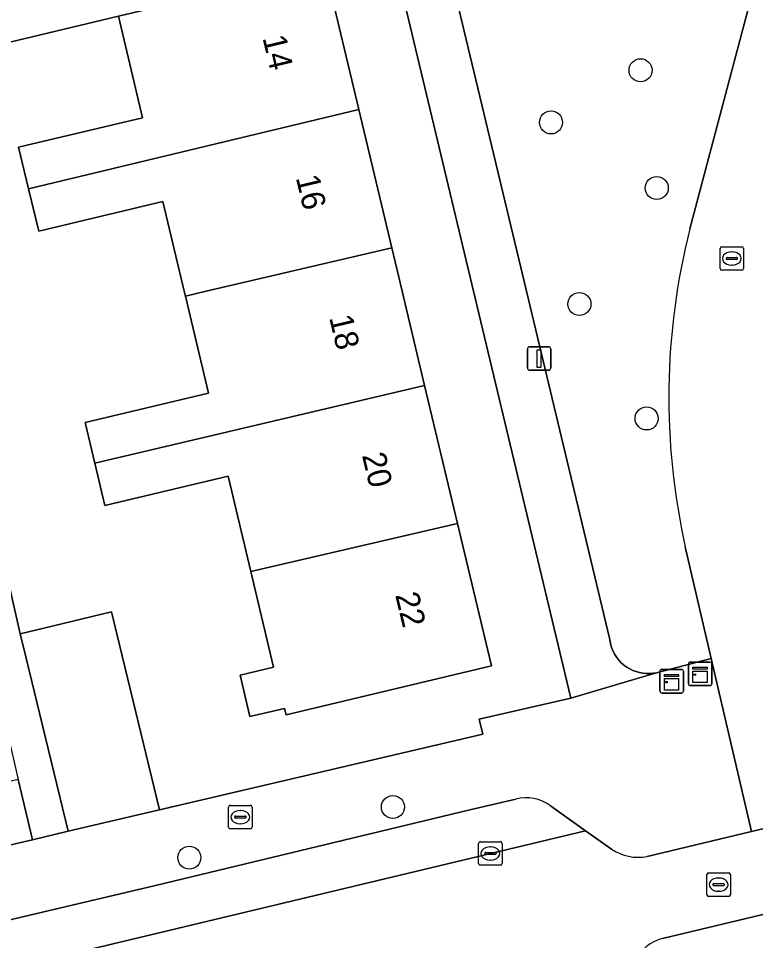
# Model space of a CAD drawing. Extents: x 158031 to 159244, y 380104 to 381214.
# Drawn here: x 158653.35 to 158684.67, y 380722.4 to 380761.59 of the extents above; entities that cross this region are included whole.
import ezdxf

# ---------------------------------------------------------------- set-up
doc = ezdxf.new("R2010")
doc.units = 0
for name, color, linetype in [('IMGEO_Boom', 7, 'Continuous'), ('IMGEO_Brandkraan', 7, 'Continuous'), ('IMGEO_Erf', 7, 'Continuous'), ('IMGEO_Fietspad_open', 7, 'Continuous'), ('IMGEO_Groenvoorziening', 7, 'Continuous'), ('IMGEO_Kast', 7, 'Continuous'), ('IMGEO_Kolk', 7, 'Continuous'), ('IMGEO_Lichtmast', 7, 'Continuous'), ('IMGEO_Muur', 7, 'Continuous'), ('IMGEO_Pand', 7, 'Continuous'), ('IMGEO_Pand_nummerreeks', 7, 'Continuous'), ('IMGEO_Parkeervlak_open', 7, 'Continuous'), ('IMGEO_Rijbaan_lokaal_gesloten', 7, 'Continuous'), ('IMGEO_Rioolput', 7, 'Continuous'), ('IMGEO_Voetpad_open', 7, 'Continuous')]:
    doc.layers.add(name, color=color, linetype=linetype)

msp = doc.modelspace()

# ---------------------------------------------------------------- linework, layer by layer
at = {"layer": 'IMGEO_Boom'}
for centre in [(158679.783, 380759.387), (158675.981, 380757.169), (158680.473, 380754.38), (158677.187, 380749.451), (158680.04, 380744.588), (158669.26, 380728.079), (158660.611, 380725.925)]:
    msp.add_circle(centre, 0.489, dxfattribs=at)
at = {"layer": 'IMGEO_Brandkraan'}
for p, q in [((158662.278, 380727.221), (158662.278, 380728.073)), ((158662.353, 380728.147), (158663.205, 380728.147)), ((158663.279, 380728.073), (158663.279, 380727.221)), ((158662.537, 380727.641), (158662.537, 380727.653)), ((158662.975, 380727.604), (158662.577, 380727.604)), ((158662.58, 380727.69), (158662.978, 380727.69)), ((158662.766, 380727.927), (158662.791, 380727.927)), ((158663.021, 380727.653), (158663.021, 380727.641)), ((158662.789, 380727.367), (158662.764, 380727.367)), ((158663.205, 380727.147), (158662.353, 380727.147))]:
    msp.add_line(p, q, dxfattribs=at)
for points in [[(158662.278, 380727.221), (158662.278, 380728.073)], [(158662.353, 380728.147), (158663.205, 380728.147)], [(158663.279, 380728.073), (158663.279, 380727.221)], [(158663.205, 380727.147), (158662.353, 380727.147)]]:
    msp.add_lwpolyline(points, dxfattribs=at)
for centre, radius, start, end in [((158662.355, 380728.071), 0.0765, 91.552, 178.448), ((158662.355, 380728.071), 0.0765, 91.552, 178.448), ((158663.203, 380728.071), 0.0765, 1.552, 88.448), ((158663.203, 380728.071), 0.0765, 1.552, 88.448), ((158662.577, 380727.65), 0.0403, 85.8775, 175.7526), ((158662.574, 380727.64), 0.0366, 178.938, 274.7102), ((158662.978, 380727.647), 0.043, 264.8664, 352.4533), ((158662.982, 380727.652), 0.0386, 1.7309, 96.639), ((158662.355, 380727.223), 0.0765, 181.552, 268.448), ((158662.355, 380727.223), 0.0765, 181.552, 268.448), ((158663.203, 380727.223), 0.0765, 271.552, 358.448), ((158663.203, 380727.223), 0.0765, 271.552, 358.448)]:
    msp.add_arc(centre, radius, start, end, dxfattribs=at)
for centre, major_axis, ratio, start_param, end_param in [((158662.765, 380727.647), (-0.387, 0.002), 0.722429, 4.712389, 7.853982), ((158662.79, 380727.647), (-0.39, 0.002), 0.717154, 1.570796, 4.712389)]:
    msp.add_ellipse(centre, major_axis=major_axis, ratio=ratio, start_param=start_param, end_param=end_param, dxfattribs=at)
at = {"layer": 'IMGEO_Erf'}
for points in [[(158650.69, 380747.468), (158653.428, 380735.432), (158654.421, 380735.673), (158657.309, 380736.372), (158659.347, 380727.957), (158673.077, 380731.178), (158672.928, 380731.803), (158676.826, 380732.7), (158672.691, 380750), (158669.232, 380764.469)], [(158666.369, 380763.785), (158667.815, 380757.714), (158669.215, 380751.84), (158669.653, 380750), (158670.609, 380745.985), (158672.004, 380740.13), (158673.447, 380734.071), (158664.719, 380731.999), (158664.655, 380732.269), (158663.184, 380731.919), (158662.765, 380733.684), (158664.186, 380734.021), (158663.223, 380738.078), (158662.259, 380742.138), (158657.022, 380740.894), (158656.594, 380742.694), (158656.184, 380744.42), (158661.424, 380745.664), (158660.441, 380749.791), (158660.391, 380750), (158659.485, 380753.803), (158654.21, 380752.543), (158653.779, 380754.347), (158653.357, 380756.114), (158658.626, 380757.371), (158657.602, 380761.691), (158647.702, 380759.325)], [(158633.943, 380722.518), (158641.525, 380724.316), (158641.632, 380723.796), (158651.055, 380726.009), (158653.942, 380726.687), (158653.341, 380729.248), (158650.454, 380728.57), (158649.015, 380734.699), (158651.902, 380735.377), (158646.366, 380758.949), (158636.257, 380756.574)]]:
    msp.add_lwpolyline(points, dxfattribs=at)
at = {"layer": 'IMGEO_Fietspad_open'}
for points in [[(158706.116, 380846.84), (158705.38, 380841.883), (158704.294, 380836.939), (158703.345, 380833.438), (158702.672, 380830.956), (158702.438, 380830.095), (158702.064, 380828.716), (158698.689, 380816.265), (158694.658, 380800.796), (158694.343, 380799.586), (158694.028, 380798.377), (158693.242, 380795.503), (158691.914, 380790.494), (158681.877, 380752.64)], [(158681.687, 380739.13), (158682.788, 380734.39), (158684.497, 380727.034), (158687.897, 380727.847), (158686.923, 380732.453), (158685.37, 380739.805)]]:
    msp.add_lwpolyline(points, dxfattribs=at)
msp.add_arc((158710.112, 380745.487), 29.127, 165.7831, 192.6055, dxfattribs=at)
at = {"layer": 'IMGEO_Groenvoorziening'}
for points in [[(158681.877, 380752.64), (158691.914, 380790.494), (158676.397, 380786.904), (158675.713, 380786.597), (158675.262, 380786.166), (158674.923, 380785.504), (158674.902, 380784.494), (158679.794, 380763.903), (158677.848, 380763.441), (158672.026, 380787.946)], [(158672.055, 380762.058), (158674.94, 380750), (158678.469, 380735.251), (158678.488, 380735.105), (158678.521, 380734.961), (158678.566, 380734.82), (158678.624, 380734.685), (158678.693, 380734.554), (158678.774, 380734.431), (158678.866, 380734.315), (158678.967, 380734.208), (158679.078, 380734.111), (158679.197, 380734.023), (158679.323, 380733.947), (158679.456, 380733.882), (158679.593, 380733.829), (158679.735, 380733.789), (158679.88, 380733.762), (158680.027, 380733.748), (158680.175, 380733.747), (158680.322, 380733.759), (158680.401, 380733.771), (158682.788, 380734.39), (158681.687, 380739.13)]]:
    msp.add_lwpolyline(points, dxfattribs=at)
msp.add_arc((158710.112, 380745.487), 29.127, 165.7831, 192.6055, dxfattribs=at)
at = {"layer": 'IMGEO_Kast'}
for p, q in [((158680.679, 380733.921), (158681.52, 380733.921)), ((158681.52, 380733.921), (158680.679, 380733.921)), ((158681.815, 380733.31), (158681.815, 380734.151)), ((158681.815, 380734.151), (158681.815, 380733.31)), ((158681.89, 380734.235), (158682.731, 380734.235)), ((158682.731, 380734.235), (158681.89, 380734.235)), ((158682.815, 380734.16), (158682.815, 380733.319)), ((158682.815, 380733.319), (158682.815, 380734.16)), ((158680.604, 380732.996), (158680.604, 380733.837)), ((158680.604, 380733.837), (158680.604, 380732.996)), ((158681.604, 380733.846), (158681.604, 380733.005)), ((158681.604, 380733.005), (158681.604, 380733.846)), ((158682.74, 380733.235), (158681.899, 380733.235)), ((158681.899, 380733.235), (158682.74, 380733.235)), ((158681.529, 380732.921), (158680.688, 380732.921)), ((158680.688, 380732.921), (158681.529, 380732.921))]:
    msp.add_line(p, q, dxfattribs=at)
for points in [[(158682.01, 380734.025), (158682.61, 380734.025), (158682.61, 380733.94), (158682.01, 380733.94), (158682.01, 380734.025)], [(158682.01, 380733.85), (158682.61, 380733.85), (158682.61, 380733.361), (158682.01, 380733.361), (158682.01, 380733.85)], [(158680.799, 380733.711), (158681.399, 380733.711), (158681.399, 380733.626), (158680.799, 380733.626), (158680.799, 380733.711)], [(158680.799, 380733.536), (158681.399, 380733.536), (158681.399, 380733.047), (158680.799, 380733.047), (158680.799, 380733.536)]]:
    msp.add_lwpolyline(points, dxfattribs=at)
for centre in [(158682.094, 380733.699), (158680.883, 380733.385)]:
    msp.add_circle(centre, 0.0377, dxfattribs=at)
for centre, start, end in [((158680.682, 380733.843), 92.4484, 184.2845), ((158680.682, 380733.843), 92.4484, 184.2845), ((158681.526, 380733.843), 2.4484, 94.2845), ((158681.526, 380733.843), 2.4484, 94.2845), ((158681.893, 380734.157), 92.4484, 184.2845), ((158681.893, 380734.157), 92.4484, 184.2845), ((158682.737, 380734.157), 2.4484, 94.2845), ((158682.737, 380734.157), 2.4484, 94.2845), ((158681.893, 380733.313), 182.4484, 274.2845), ((158681.893, 380733.313), 182.4484, 274.2845), ((158682.737, 380733.313), 272.4484, 4.2845), ((158682.737, 380733.313), 272.4484, 4.2845), ((158680.682, 380732.999), 182.4484, 274.2845), ((158680.682, 380732.999), 182.4484, 274.2845), ((158681.526, 380732.999), 272.4484, 4.2845), ((158681.526, 380732.999), 272.4484, 4.2845)]:
    msp.add_arc(centre, 0.0779, start, end, dxfattribs=at)
at = {"layer": 'IMGEO_Kolk'}
for p, q in [((158672.902, 380725.677), (158672.902, 380726.529)), ((158672.977, 380726.603), (158673.829, 380726.603)), ((158673.903, 380726.529), (158673.903, 380725.677)), ((158673.161, 380726.097), (158673.161, 380726.109)), ((158673.599, 380726.06), (158673.201, 380726.06)), ((158673.204, 380726.146), (158673.602, 380726.146)), ((158673.39, 380726.383), (158673.415, 380726.383)), ((158673.645, 380726.109), (158673.645, 380726.097)), ((158673.413, 380725.823), (158673.388, 380725.823)), ((158673.829, 380725.603), (158672.977, 380725.603))]:
    msp.add_line(p, q, dxfattribs=at)
for points in [[(158672.902, 380725.677), (158672.902, 380726.529)], [(158672.977, 380726.603), (158673.829, 380726.603)], [(158673.903, 380726.529), (158673.903, 380725.677)], [(158673.829, 380725.603), (158672.977, 380725.603)]]:
    msp.add_lwpolyline(points, dxfattribs=at)
for centre, radius, start, end in [((158672.979, 380726.527), 0.0765, 91.552, 178.448), ((158672.979, 380726.527), 0.0765, 91.552, 178.448), ((158673.827, 380726.527), 0.0765, 1.552, 88.448), ((158673.827, 380726.527), 0.0765, 1.552, 88.448), ((158673.201, 380726.106), 0.0403, 85.8775, 175.7526), ((158673.198, 380726.096), 0.0366, 178.938, 274.7102), ((158673.602, 380726.103), 0.043, 264.8664, 352.4533), ((158673.606, 380726.108), 0.0386, 1.7309, 96.639), ((158672.979, 380725.679), 0.0765, 181.552, 268.448), ((158672.979, 380725.679), 0.0765, 181.552, 268.448), ((158673.827, 380725.679), 0.0765, 271.552, 358.448), ((158673.827, 380725.679), 0.0765, 271.552, 358.448)]:
    msp.add_arc(centre, radius, start, end, dxfattribs=at)
for centre, major_axis, ratio, start_param, end_param in [((158673.389, 380726.103), (-0.387, 0.002), 0.722429, 4.712389, 7.853982), ((158673.414, 380726.103), (-0.39, 0.002), 0.717154, 1.570796, 4.712389)]:
    msp.add_ellipse(centre, major_axis=major_axis, ratio=ratio, start_param=start_param, end_param=end_param, dxfattribs=at)
at = {"layer": 'IMGEO_Lichtmast'}
for p, q in [((158675.078, 380747.635), (158675.868, 380747.635)), ((158675.868, 380747.635), (158675.078, 380747.635)), ((158674.978, 380746.735), (158674.978, 380747.535)), ((158674.978, 380747.535), (158674.978, 380746.735)), ((158675.968, 380747.535), (158675.968, 380746.735)), ((158675.968, 380746.735), (158675.968, 380747.535)), ((158675.868, 380746.635), (158675.078, 380746.635)), ((158675.078, 380746.635), (158675.868, 380746.635))]:
    msp.add_line(p, q, dxfattribs=at)
msp.add_lwpolyline([(158675.398, 380747.51), (158675.548, 380747.51), (158675.548, 380746.76), (158675.398, 380746.76), (158675.398, 380747.51)], dxfattribs=at)
for centre, start, end in [((158675.078, 380747.535), 90, 180), ((158675.078, 380747.535), 90, 180), ((158675.868, 380747.535), 0, 90), ((158675.868, 380747.535), 360, 90), ((158675.078, 380746.735), 180, 270), ((158675.078, 380746.735), 180, 270), ((158675.868, 380746.735), 270, 0), ((158675.868, 380746.735), 270, 0)]:
    msp.add_arc(centre, 0.1, start, end, dxfattribs=at)
at = {"layer": 'IMGEO_Muur'}
msp.add_lwpolyline([(158658.308, 380727.713), (158673.077, 380731.178)], dxfattribs=at)
at = {"layer": 'IMGEO_Pand'}
for points in [[(158653.779, 380754.347), (158667.815, 380757.714), (158666.369, 380763.785), (158661.506, 380762.624), (158657.602, 380761.691), (158658.626, 380757.371), (158653.357, 380756.114)], [(158660.441, 380749.791), (158661.329, 380750), (158669.215, 380751.84), (158667.815, 380757.714), (158653.779, 380754.347), (158654.21, 380752.543), (158659.485, 380753.803), (158660.391, 380750)], [(158670.609, 380745.985), (158669.653, 380750), (158669.215, 380751.84), (158661.329, 380750), (158660.441, 380749.791), (158661.424, 380745.664), (158656.184, 380744.42), (158656.594, 380742.694)], [(158670.609, 380745.985), (158656.594, 380742.694), (158657.022, 380740.894), (158662.259, 380742.138), (158663.223, 380738.078), (158672.004, 380740.13)], [(158672.004, 380740.13), (158663.223, 380738.078), (158664.186, 380734.021), (158662.765, 380733.684), (158663.184, 380731.919), (158664.655, 380732.269), (158664.719, 380731.999), (158673.447, 380734.071)], [(158655.46, 380727.044), (158658.308, 380727.713), (158659.347, 380727.957), (158657.309, 380736.372), (158654.421, 380735.673), (158653.428, 380735.432), (158653.664, 380734.459)]]:
    msp.add_lwpolyline(points, close=True, dxfattribs=at)
at = {"layer": 'IMGEO_Parkeervlak_open'}
for points in [[(158674.479, 380728.406), (158672.524, 380727.961), (158659.175, 380724.742), (158651.834, 380723.01), (158640.223, 380720.27)], [(158677.444, 380727.07), (158675.955, 380728.122)], [(158637.203, 380717.466), (158653.812, 380721.407), (158677.444, 380727.07)]]:
    msp.add_lwpolyline(points, dxfattribs=at)
msp.add_arc((158674.943, 380726.842), 1.632, 51.6848, 106.5326, dxfattribs=at)
at = {"layer": 'IMGEO_Rijbaan_lokaal_gesloten'}
for points in [[(158691.185, 380728.633), (158687.897, 380727.847), (158684.497, 380727.034), (158680.059, 380725.973)], [(158678.552, 380726.287), (158677.444, 380727.07), (158653.812, 380721.407), (158637.203, 380717.466), (158637.007, 380717.42), (158638.594, 380710.645), (158678.337, 380720.133)], [(158680.713, 380722.488), (158685.569, 380723.649), (158688.969, 380724.462), (158692.194, 380725.233)]]:
    msp.add_lwpolyline(points, dxfattribs=at)
for centre, radius, start, end in [((158679.687, 380727.96), 2.021, 235.8457, 280.6146), ((158681.215, 380720.647), 1.909, 105.259, 151.3055)]:
    msp.add_arc(centre, radius, start, end, dxfattribs=at)
at = {"layer": 'IMGEO_Rioolput'}
for p, q in [((158683.237, 380751.886), (158684.089, 380751.886)), ((158683.162, 380750.96), (158683.162, 380751.812)), ((158683.65, 380751.666), (158683.675, 380751.666)), ((158684.163, 380751.812), (158684.163, 380750.96)), ((158683.421, 380751.38), (158683.421, 380751.392)), ((158683.859, 380751.343), (158683.461, 380751.343)), ((158683.464, 380751.429), (158683.862, 380751.429)), ((158683.673, 380751.106), (158683.648, 380751.106)), ((158683.905, 380751.392), (158683.905, 380751.38)), ((158684.089, 380750.886), (158683.237, 380750.886)), ((158682.678, 380725.276), (158683.53, 380725.276)), ((158682.603, 380724.35), (158682.603, 380725.202)), ((158683.091, 380725.056), (158683.116, 380725.056)), ((158683.604, 380725.202), (158683.604, 380724.35)), ((158682.862, 380724.77), (158682.862, 380724.782)), ((158683.3, 380724.733), (158682.902, 380724.733)), ((158682.905, 380724.819), (158683.303, 380724.819)), ((158683.114, 380724.496), (158683.089, 380724.496)), ((158683.346, 380724.782), (158683.346, 380724.77)), ((158683.53, 380724.276), (158682.678, 380724.276))]:
    msp.add_line(p, q, dxfattribs=at)
for points in [[(158683.237, 380751.886), (158684.089, 380751.886)], [(158683.162, 380750.96), (158683.162, 380751.812)], [(158684.163, 380751.812), (158684.163, 380750.96)], [(158684.089, 380750.886), (158683.237, 380750.886)], [(158682.678, 380725.276), (158683.53, 380725.276)], [(158682.603, 380724.35), (158682.603, 380725.202)], [(158683.604, 380725.202), (158683.604, 380724.35)], [(158683.53, 380724.276), (158682.678, 380724.276)]]:
    msp.add_lwpolyline(points, dxfattribs=at)
for centre, radius, start, end in [((158683.239, 380751.81), 0.0765, 91.552, 178.448), ((158683.239, 380751.81), 0.0765, 91.552, 178.448), ((158684.087, 380751.81), 0.0765, 1.552, 88.448), ((158684.087, 380751.81), 0.0765, 1.552, 88.448), ((158683.461, 380751.389), 0.0403, 85.8775, 175.7526), ((158683.458, 380751.379), 0.0366, 178.938, 274.7102), ((158683.862, 380751.386), 0.043, 264.8664, 352.4533), ((158683.866, 380751.391), 0.0386, 1.7309, 96.639), ((158683.239, 380750.962), 0.0765, 181.552, 268.448), ((158683.239, 380750.962), 0.0765, 181.552, 268.448), ((158684.087, 380750.962), 0.0765, 271.552, 358.448), ((158684.087, 380750.962), 0.0765, 271.552, 358.448), ((158682.68, 380725.2), 0.0765, 91.552, 178.448), ((158682.68, 380725.2), 0.0765, 91.552, 178.448), ((158683.528, 380725.2), 0.0765, 1.552, 88.448), ((158683.528, 380725.2), 0.0765, 1.552, 88.448), ((158682.902, 380724.779), 0.0403, 85.8775, 175.7526), ((158682.899, 380724.769), 0.0366, 178.938, 274.7102), ((158683.303, 380724.776), 0.043, 264.8664, 352.4533), ((158683.307, 380724.781), 0.0386, 1.7309, 96.639), ((158682.68, 380724.352), 0.0765, 181.552, 268.448), ((158682.68, 380724.352), 0.0765, 181.552, 268.448), ((158683.528, 380724.352), 0.0765, 271.552, 358.448), ((158683.528, 380724.352), 0.0765, 271.552, 358.448)]:
    msp.add_arc(centre, radius, start, end, dxfattribs=at)
for centre, major_axis, ratio, start_param, end_param in [((158683.649, 380751.386), (-0.387, 0.002), 0.722429, 4.712389, 7.853982), ((158683.674, 380751.386), (-0.39, 0.002), 0.717154, 1.570796, 4.712389), ((158683.09, 380724.776), (-0.387, 0.002), 0.722429, 4.712389, 7.853982), ((158683.115, 380724.776), (-0.39, 0.002), 0.717154, 1.570796, 4.712389)]:
    msp.add_ellipse(centre, major_axis=major_axis, ratio=ratio, start_param=start_param, end_param=end_param, dxfattribs=at)
at = {"layer": 'IMGEO_Voetpad_open'}
msp.add_lwpolyline([(158657.602, 380761.691), (158661.506, 380762.624), (158666.369, 380763.785), (158669.232, 380764.469), (158668.932, 380765.724), (158656.209, 380762.733), (158633.152, 380757.312), (158627.044, 380755.876), (158624.245, 380755.218), (158624.571, 380753.829), (158627.557, 380754.53), (158632.414, 380755.671), (158636.257, 380756.574), (158646.366, 380758.949), (158651.902, 380735.377), (158653.341, 380729.248), (158653.942, 380726.687), (158655.46, 380727.044), (158653.664, 380734.459), (158653.428, 380735.432), (158650.69, 380747.468), (158649.557, 380751.964), (158647.702, 380759.325)], close=True, dxfattribs=at)
for points in [[(158669.232, 380764.469), (158672.691, 380750), (158676.826, 380732.7), (158680.401, 380733.771), (158680.322, 380733.759), (158680.175, 380733.747), (158680.027, 380733.748), (158679.88, 380733.762), (158679.735, 380733.789), (158679.593, 380733.829), (158679.456, 380733.882), (158679.323, 380733.947), (158679.197, 380734.023), (158679.078, 380734.111), (158678.967, 380734.208), (158678.866, 380734.315), (158678.774, 380734.431), (158678.693, 380734.554), (158678.624, 380734.685), (158678.566, 380734.82), (158678.521, 380734.961), (158678.488, 380735.105), (158678.469, 380735.251), (158674.94, 380750), (158672.055, 380762.058)], [(158680.059, 380725.973), (158684.497, 380727.034), (158682.788, 380734.39), (158680.401, 380733.771), (158676.826, 380732.7), (158672.928, 380731.803), (158673.077, 380731.178), (158659.347, 380727.957), (158658.308, 380727.713), (158655.46, 380727.044), (158653.942, 380726.687), (158651.055, 380726.009), (158641.632, 380723.796), (158641.525, 380724.316), (158633.943, 380722.518), (158627.912, 380720.355)], [(158659.175, 380724.742), (158672.524, 380727.961), (158674.479, 380728.406)], [(158675.955, 380728.122), (158677.444, 380727.07), (158678.552, 380726.287)], [(158640.223, 380720.27), (158651.834, 380723.01), (158659.175, 380724.742)], [(158646.034, 380709.321), (158649.457, 380710.132), (158670.862, 380715.31), (158686.652, 380719.032), (158685.569, 380723.649), (158680.713, 380722.488)]]:
    msp.add_lwpolyline(points, dxfattribs=at)
for centre, radius, start, end in [((158674.943, 380726.842), 1.632, 51.6848, 106.5326), ((158679.687, 380727.96), 2.021, 235.8457, 280.6146), ((158681.215, 380720.647), 1.909, 105.259, 151.3055)]:
    msp.add_arc(centre, radius, start, end, dxfattribs=at)

# ---------------------------------------------------------------- texts
at = {"layer": 'IMGEO_Pand_nummerreeks'}
for s, p in [('14', (158663.716, 380760.769)), ('16', (158665.131, 380754.826)), ('18', (158666.548, 380748.88)), ('20', (158667.943, 380743.025)), ('22', (158669.356, 380737.088))]:
    msp.add_text(s, height=1, rotation=283.3984, dxfattribs=at).set_placement(p)

doc.saveas('drawing.dxf')
